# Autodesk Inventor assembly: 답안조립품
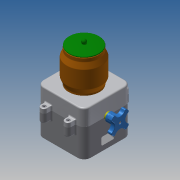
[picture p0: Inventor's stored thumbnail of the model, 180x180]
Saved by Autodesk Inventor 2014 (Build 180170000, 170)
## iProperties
Created: 2018-01
Part Number: 답안조립품
Document SubType Name: Assembly
Designer: kb542
Author: kb542
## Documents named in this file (9)
- C:\Users\kb542\Desktop\480107V1045\답안조립품.iam
- C:\Users\kb542\Desktop\480107V1045\본체.ipt
- C:\Users\kb542\Desktop\480107V1045\본체커버.ipt
- C:\Users\kb542\Desktop\480107V1045\볼트 M3x12.ipt
- C:\Users\kb542\Desktop\480107V1045\볼트 M4x12.ipt
- C:\Users\kb542\Desktop\480107V1045\용기.ipt
- C:\Users\kb542\Desktop\480107V1045\용기캡.ipt
- C:\Users\kb542\Desktop\480107V1045\핸들.ipt
- C:\Users\kb542\Desktop\480107V1045\핸들축.ipt
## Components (2 placed, 2 different names)
1. 핸들:1
2. 핸들축:1 — 플러쉬:1
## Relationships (1: Flush 1)
- 플러쉬:1 [Flush]: 핸들축:1
